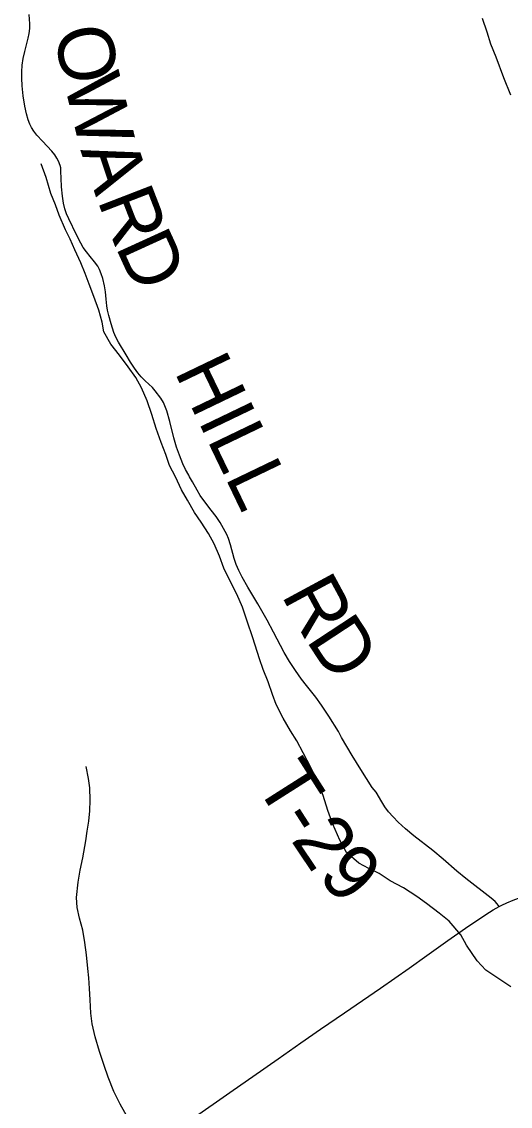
# Model space of a CAD drawing. Extents: x 0 to 34, y 0 to 22.
# Drawn here: x 7.454 to 7.947, y 15.927 to 17.022 of the extents above; entities that cross this region are included whole.
import ezdxf

# ---------------------------------------------------------------- set-up
doc = ezdxf.new("R2010")
doc.units = 0
for name, color, linetype in [('GM_X_County_Road', 7, 'Continuous'), ('GM_X_Minor_River', 7, 'Continuous'), ('GM_X_Township_Road', 7, 'Continuous'), ('GM_X_Township_Road_Text', 7, 'Continuous')]:
    doc.layers.add(name, color=color, linetype=linetype)

msp = doc.modelspace()

# ---------------------------------------------------------------- linework, layer by layer
at = {"layer": 'GM_X_County_Road'}
for points in [[(7.9354, 16.129), (7.938, 16.1303), (7.9432, 16.1327), (7.9496, 16.1354), (7.9578, 16.1383), (7.9814, 16.1462), (7.989, 16.149), (8.0265, 16.1637), (8.0575, 16.1764), (8.0741, 16.1835), (8.0823, 16.1866), (8.0889, 16.1887), (8.0949, 16.1902), (8.1017, 16.1913), (8.1129, 16.1926), (8.1327, 16.1943), (8.1348, 16.1945)], [(7.6223, 15.9122), (7.6671, 15.9435), (7.6869, 15.9574), (7.7124, 15.9752), (7.7353, 15.9912), (7.7551, 16.0051), (7.7793, 16.0215), (7.8157, 16.0464), (7.8447, 16.0667), (7.8624, 16.0793), (7.8835, 16.0947), (7.9014, 16.1071), (7.922, 16.1209), (7.9294, 16.1256), (7.9354, 16.129)]]:
    msp.add_lwpolyline(points, dxfattribs=at)
at = {"layer": 'GM_X_Minor_River'}
for points in [[(7.9473, 16.9477), (7.9403, 16.9653), (7.9323, 16.9859), (7.9272, 16.9993), (7.9232, 17.0111), (7.9185, 17.0249)], [(7.9471, 16.0478), (7.937, 16.0544), (7.9219, 16.0645), (7.9134, 16.0741), (7.9026, 16.0899), (7.8967, 16.1002), (7.8851, 16.114), (7.875, 16.1222), (7.8622, 16.1318), (7.8525, 16.1388), (7.839, 16.1478), (7.8254, 16.1548), (7.8145, 16.1622), (7.804, 16.1673), (7.7938, 16.1727), (7.7815, 16.1835), (7.7748, 16.1958), (7.7675, 16.2119), (7.7624, 16.2256), (7.7577, 16.2409), (7.7514, 16.2565), (7.7459, 16.2684), (7.7378, 16.2841), (7.7312, 16.296), (7.7249, 16.3063), (7.7175, 16.3189), (7.7105, 16.3327), (7.7068, 16.3427), (7.7025, 16.3556), (7.6973, 16.3679), (7.6937, 16.3789), (7.6868, 16.3999), (7.681, 16.4167), (7.6766, 16.4308), (7.6707, 16.4439), (7.6641, 16.4572), (7.6575, 16.4703), (7.6531, 16.4825), (7.648, 16.4947), (7.6421, 16.5054), (7.6347, 16.5169), (7.628, 16.5265), (7.6209, 16.5388), (7.615, 16.5495), (7.6088, 16.5625), (7.6029, 16.574), (7.5992, 16.5851), (7.5945, 16.5973), (7.5894, 16.6114), (7.585, 16.6255), (7.5803, 16.6393), (7.5744, 16.6523), (7.5689, 16.6626), (7.5611, 16.6734), (7.5525, 16.6853), (7.5436, 16.6964), (7.5366, 16.7087), (7.5348, 16.7186), (7.5316, 16.7308), (7.5265, 16.7445), (7.5217, 16.7568), (7.5177, 16.7678), (7.5133, 16.7785), (7.5074, 16.7915), (7.5027, 16.8023), (7.4979, 16.8118), (7.4913, 16.8267), (7.4876, 16.837), (7.4829, 16.8485), (7.4782, 16.8645), (7.4734, 16.8783)], [(7.5607, 15.9155), (7.5529, 15.9293), (7.5467, 15.9423), (7.5408, 15.9565), (7.5368, 15.9683), (7.5321, 15.9824), (7.5277, 15.9973), (7.5249, 16.0103), (7.5235, 16.0213), (7.5226, 16.0346), (7.522, 16.046), (7.5214, 16.0567), (7.5204, 16.0662), (7.5191, 16.0802), (7.5174, 16.0924), (7.5153, 16.105), (7.5121, 16.1172), (7.5096, 16.1279), (7.5089, 16.1378), (7.5107, 16.1533), (7.5128, 16.1654), (7.5152, 16.1779), (7.5185, 16.195), (7.5198, 16.2048), (7.5214, 16.2151), (7.5223, 16.2253), (7.5229, 16.2363), (7.5223, 16.2485), (7.5209, 16.258), (7.5188, 16.2702)]]:
    msp.add_lwpolyline(points, dxfattribs=at)
at = {"layer": 'GM_X_Township_Road'}
for points in [[(7.6231, 16.5624), (7.6222, 16.564), (7.6189, 16.5699), (7.6163, 16.5756), (7.6128, 16.5842), (7.6099, 16.5924), (7.6071, 16.6019), (7.603, 16.6182), (7.6, 16.629), (7.5982, 16.6342), (7.5966, 16.6376), (7.594, 16.6418), (7.5884, 16.6493), (7.5855, 16.6526), (7.5782, 16.6593), (7.5743, 16.6633), (7.5708, 16.6676), (7.5675, 16.672), (7.5634, 16.6783), (7.559, 16.6857), (7.5512, 16.6985), (7.5486, 16.7034), (7.5467, 16.708), (7.5438, 16.7169), (7.5415, 16.7253), (7.5403, 16.7307), (7.5397, 16.735), (7.539, 16.7418), (7.5382, 16.7492), (7.5371, 16.7553), (7.5355, 16.7626), (7.534, 16.7673), (7.5322, 16.7719), (7.5304, 16.775), (7.5272, 16.7795), (7.5229, 16.7848), (7.519, 16.7896), (7.5158, 16.7941), (7.5132, 16.7983), (7.5091, 16.8066), (7.5011, 16.8227), (7.499, 16.8278), (7.4973, 16.8331), (7.496, 16.8386), (7.4948, 16.8459), (7.4939, 16.8552), (7.4934, 16.8639), (7.4933, 16.8707), (7.493, 16.8744), (7.4925, 16.8768), (7.4909, 16.8809), (7.4892, 16.8842), (7.4872, 16.8873), (7.4841, 16.8912), (7.4747, 16.9011), (7.4689, 16.9074), (7.4658, 16.9113), (7.4635, 16.9149), (7.4618, 16.9183), (7.4601, 16.9229), (7.4584, 16.9288), (7.4568, 16.9367), (7.4552, 16.9471), (7.4541, 16.957), (7.4537, 16.965), (7.4537, 16.9712), (7.4542, 16.9779), (7.4552, 16.9847), (7.4567, 16.9919), (7.4603, 17.0051), (7.4613, 17.0099), (7.4619, 17.0148), (7.4619, 17.0198), (7.4612, 17.029)], [(7.9354, 16.129), (7.9334, 16.1316), (7.9314, 16.1338), (7.9275, 16.1371), (7.9017, 16.157), (7.8928, 16.1644), (7.8789, 16.1765), (7.8686, 16.1853), (7.8495, 16.2001), (7.8409, 16.2072), (7.8336, 16.2139), (7.8284, 16.2192), (7.8239, 16.2244), (7.8202, 16.2294), (7.8169, 16.2346), (7.8113, 16.2442), (7.8074, 16.2488), (7.7959, 16.2671), (7.7871, 16.2814), (7.7764, 16.2995), (7.7755, 16.3015), (7.7732, 16.3056), (7.7636, 16.3208), (7.7561, 16.3321), (7.7503, 16.3402), (7.7409, 16.3518), (7.736, 16.3582), (7.73, 16.3669), (7.7239, 16.3762), (7.7185, 16.3853), (7.7078, 16.4057), (7.7014, 16.4178), (7.6919, 16.4344), (7.6819, 16.451), (7.6761, 16.4612), (7.6727, 16.4679), (7.6701, 16.4741), (7.6681, 16.48), (7.6643, 16.4938), (7.6622, 16.5003), (7.6605, 16.5043), (7.6574, 16.5104), (7.6539, 16.5163), (7.6498, 16.5224), (7.6449, 16.5288), (7.6384, 16.5371), (7.6338, 16.5437), (7.6306, 16.5489), (7.6259, 16.5576), (7.6231, 16.5624)]]:
    msp.add_lwpolyline(points, dxfattribs=at)

# ---------------------------------------------------------------- texts
at = {"layer": 'GM_X_Township_Road_Text'}
for s, height, rotation, p in [('O', 0.0568, 281.3123, (7.4857, 17.0128)), ('W', 0.0568, 283.5447, (7.496, 16.9614)), ('A', 0.0568, 288.3108, (7.5128, 16.8924)), ('R', 0.0568, 291.1449, (7.5296, 16.842)), ('D', 0.0568, 294.5446, (7.5478, 16.7951)), ('HILL', 0.05682, 295.6848, (7.6072, 16.669)), ('R', 0.0568, 298.3907, (7.715, 16.4435)), ('D', 0.0568, 303.3236, (7.7398, 16.398)), ('T', 0.0568, 302.4366, (7.6884, 16.2529)), ('-', 0.0568, 302.6415, (7.7113, 16.2168)), ('2', 0.0568, 303.8449, (7.7246, 16.1961)), ('9', 0.0568, 314.0413, (7.751, 16.1584))]:
    msp.add_text(s, height=height, rotation=rotation, dxfattribs=at).set_placement(p)

doc.saveas('drawing.dxf')
